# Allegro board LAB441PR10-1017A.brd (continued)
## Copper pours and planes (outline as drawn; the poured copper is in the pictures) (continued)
LG_5V on BOTTOM (solid shape): 61.56,53.99 61.82,53.99 61.94,53.86 61.94,52.97 61.82,52.85 61.43,52.85 60.35,53.93 60.35,54.12 60.42,54.18 61.37,54.18
LG_5V on IN3 (solid shape): 62.83,53.29 62.83,52.47 62.7,52.34 62.01,52.34 61.43,52.91 61.43,53.93 61.56,54.05 62.07,54.05
LG_5V on IN3 (solid shape): 68.8,49.73 68.8,48.46 68.67,48.34 68.42,48.34 67.15,49.61 67.15,50.12 67.53,50.5 68.04,50.5
LX_1.05V on TOP (solid shape): 204.31,59.64 204.31,57.48 204.18,57.35 203.29,57.35 203.17,57.48 203.17,59.64 203.29,59.77 204.18,59.77
LX_1.05V on BOTTOM (solid shape): 201.13,61.16 201.77,60.53 204.06,60.53 205.07,59.51 205.07,55.58 204.82,55.32 200.63,55.32 199.99,55.96 199.99,62.43 201.13,62.43
LX_3V on BOTTOM (solid shape): 65.37,56.72 65.37,56.28 64.8,55.7 64.42,55.7 64.29,55.83 64.29,56.78 64.36,56.85 65.24,56.85
LX_3V on BOTTOM (solid shape): 59.15,59.2 59.15,58.18 59.47,57.86 59.47,55.89 59.4,55.83 59.34,55.83 59.28,55.89 59.28,56.91 58.89,57.29 58.89,57.67 58.39,58.18 58.39,59.2 58.45,59.26 59.08,59.26
LX_3V on IN4 (solid shape): 64.86,57.61 64.86,55.83 64.74,55.7 64.36,55.7 64.1,55.96 64.1,56.85 63.72,57.23 63.72,57.48 64.23,57.99 64.48,57.99
LX_3V on IN4 (solid shape): 60.16,58.62 60.16,58.24 59.66,57.74 59.66,57.35 59.4,57.1 59.02,57.1 58.89,57.23 58.89,57.61 58.64,57.86 58.64,58.24 59.4,59.01 59.78,59.01
LX_5V on BOTTOM (solid shape): 70.01,53.35 70.01,52.97 69.82,52.78 68.42,52.78 68.29,52.91 68.29,53.35 68.42,53.48 69.88,53.48
LX_5V on BOTTOM (solid shape): 59.47,53.8 59.47,52.78 59.59,52.66 59.59,51.58 59.72,51.45 59.72,50.88 59.66,50.81 59.15,50.81 59.08,50.88 59.08,52.59 59.28,52.78 59.28,53.8 59.34,53.86 59.4,53.86
LX_5V on IN4 (solid shape): 59.66,52.66 59.66,51.89 60.16,51.39 60.16,50.88 59.78,50.5 59.53,50.5 59.02,51 59.02,52.66 59.15,52.78 59.53,52.78
LX_5V on IN4 (solid shape): 70.01,53.29 70.01,52.15 69.82,51.96 69.05,51.96 68.86,52.15 68.86,53.23 68.99,53.35 69.94,53.35
LX_CORE on TOP (solid shape): 94.26,59.7 94.26,58.24 94.07,58.05 92.68,58.05 92.42,58.31 92.42,59.77 92.49,59.83 94.14,59.83
LX_CORE on BOTTOM (solid shape): 95.72,59.45 95.72,55.89 96.61,55.89 96.61,58.82 96.8,59.01 98.33,59.01 98.96,58.37 98.96,55.07 98.39,54.5 92.49,54.5 91.22,55.77 91.22,56.81 91.03,57 91.03,59.96 95.22,59.96
MIC1_L on TOP (solid shape): 27.13,27.87 27.93,27.87 27.93,27.86 28.3,27.86 28.36,27.79 28.36,27.72 28.29,27.64 25.92,27.64 25.82,27.74 25.82,28.01 25.9,28.09 26.9,28.09
MIC1_L on BOTTOM (solid shape): 14.23,24.46 14.23,23.74 14.08,23.58 11.9,23.58 11.9,23.59 11.34,23.59 11.34,23.58 11.3,23.58 11.18,23.7 11.18,24.44 11.38,24.63 14.06,24.63
MIC1_L on IN2 (solid shape): 15.19,24.58 15.19,23.8 14.98,23.59 13.32,23.59 13.14,23.77 13.14,24.51 13.34,24.7 15.07,24.7
MIC1_L on IN2 (solid shape): 24.99,28.66 25.21,28.5 25.46,28.56 25.5,28.58 25.98,28.1 26.69,28.1 26.84,27.96 26.84,27.78 26.7,27.64 24.82,27.64 24.82,27.64 24.48,27.64 24.36,27.76 24.36,28.52 24.49,28.66
MIC1_L_L on TOP (solid shape): 12.12,23.65 12.12,22.4 11.93,22.21 11.17,22.21 11,22.39 11,23.55 11.31,23.86 11.91,23.86
MIC1_L_L on TOP (solid shape): 16.45,27.78 16.45,26.42 16.24,26.2 15.66,26.2 15.39,26.47 15.39,27.71 15.59,27.91 16.32,27.91
MIC1_L_L on BOTTOM (solid shape): 6.39,24.6 7.92,24.6 9.01,23.5 9.97,23.5 10.05,23.41 11.13,23.41 11.19,23.36 11.98,23.36 12.1,23.24 12.1,22.36 11.97,22.23 11.13,22.23 10.86,22.5 8.45,22.5 7.96,22.98 7.96,22.98 7.45,23.49 5.78,23.49 4.87,24.41 3.78,24.41 3.47,24.71 3.47,25.79 3.57,25.89 5.1,25.89
MIC1_R on TOP (solid shape): 9.52,22.58 9.52,21.24 9.43,21.15 8.39,21.15 8.11,21.43 8.11,23.06 8.17,23.12 8.97,23.12
MIC1_R on TOP (solid shape): 27.4,27.49 27.69,27.49 27.71,27.47 28.31,27.47 28.37,27.41 28.37,27.31 28.3,27.23 26.89,27.23 26.71,27.06 25.9,27.06 25.79,27.16 25.79,27.44 25.87,27.52 27.37,27.52
MIC1_R on BOTTOM (solid shape): 12.45,21.62 14.02,21.62 14.25,21.39 14.25,20.59 14.09,20.42 13.01,20.42 13,20.43 12.36,20.79 11.65,21.03 11.64,21.03 11.52,21.15 8.46,21.15 8.29,21.33 8.29,21.88 8.4,21.99 12.08,21.99
MIC1_R on IN2 (solid shape): 15.21,21.34 15.21,20.85 14.76,20.39 13.21,20.39 13.08,20.51 13.08,21.46 13.19,21.57 14.99,21.57
MIC1_R on IN2 (solid shape): 26.86,27.37 26.86,27.21 26.71,27.06 25.75,27.06 25.2,26.51 24.69,26.51 24.53,26.66 24.53,27.43 24.63,27.52 26.7,27.52
MIC1_R_L on TOP (solid shape): 17.99,25.97 18.07,25.89 18.07,24.48 17.99,24.41 17.04,24.41 16.99,24.45 16.99,24.9 17.29,25.2 17.29,25.9 17.36,25.97 17.6,25.97
MIC1_R_L on TOP (solid shape): 8.41,25.78 8.41,25.22 10.78,22.85 10.78,22.43 11.14,22.07 12.19,22.07 12.33,21.93 12.33,21.13 12.21,21.01 11.71,21.01 11.61,21.04 11.52,21.06 11.41,21.16 9.93,21.16 9.75,21.34 9.75,22.53 8.9,23.37 8.31,23.37 8.24,23.3 6.3,23.3 6.16,23.44 6.16,25.78 6.42,26.03 8.16,26.03
PBATT+_C on TOP (solid shape): 73.13,29.6 73.13,27.3 72.73,26.89 70.48,26.89 70.17,27.2 70.17,29.52 70.72,30.07 72.66,30.07
PBATT+_C on BOTTOM (solid shape): 73.77,31.48 73.77,24.29 73.38,23.9 72.69,23.9 71.22,22.43 69.81,22.43 69.69,22.55 69.69,30.67 69.69,30.67 69.78,30.76 72.23,30.76 72.99,31.52 73.73,31.52
SNUB_1.5V on TOP (solid shape): 197.17,66.44 197.17,64.65 197.06,64.54 196.56,64.54 196.51,64.59 196.51,65.27 196.25,65.54 195.64,65.54 195.53,65.64 195.53,66.46 195.57,66.49 197.12,66.49
SPK_L+_C on TOP (solid shape): 28.25,21.61 28.25,20.63 27.85,20.23 26.09,20.23 26.08,20.23 25.73,20.23 24.54,19.05 22.99,19.05 21.94,18 21.94,16.58 21.65,16.29 20.05,16.29 19.86,16.48 19.86,17.67 20.26,18.08 20.6,18.08 21.27,18.75 21.28,18.76 21.42,18.84 21.51,18.98 21.51,18.99 22.28,19.76 23.4,19.76 23.59,19.71 23.77,19.76 23.97,19.76 25.31,21.1 26.74,21.1 26.98,21.34 26.98,21.5 27.14,21.67 28.19,21.67
SPK_L+_C on BOTTOM (solid shape): 27.08,17.82 27.08,16.72 26.86,16.5 25.63,16.5 25.11,17.02 24.02,17.02 23.35,16.34 23.13,16.34 23.13,16.34 19.98,16.34 19.84,16.48 19.84,17.5 20.05,17.7 20.81,17.7 21.18,17.33 23.35,17.33 23.89,17.88 27.02,17.88
SPK_L-_C on TOP (solid shape): 27.79,19.9 28.1,19.9 28.21,19.78 28.21,18.93 27.38,18.1 23.42,18.1 23.13,17.8 23.13,14.51 22.65,14.03 19.91,14.03 19.79,14.14 19.79,15.4 20.02,15.63 22.03,15.63 22.13,15.73 22.13,17.88 23.13,18.88 24.83,18.88 25.14,19.19 26.65,19.19 27.01,19.55 27.01,19.81 27.1,19.9 27.79,19.9
SPK_L-_C on BOTTOM (solid shape): 25.71,16.2 26.94,16.2 27.05,16.09 27.05,15.6 26.94,15.49 25.55,15.49 25.1,15.95 24.12,15.95 22.25,14.08 19.9,14.08 19.8,14.18 19.8,15.41 20.02,15.63 22.89,15.63 24.15,16.89 25.02,16.89
SPK_OUT_L+ on TOP (solid shape): 30.59,24.83 30.59,23.83 30.51,23.75 30.51,23.19 29.11,21.79 29.11,20.59 28.99,20.46 28.41,20.46 28.35,20.52 28.35,21.86 30,23.51 30,23.65 30.33,23.98 30.33,24.82 30.38,24.88 30.54,24.88
SPK_OUT_L- on TOP (solid shape): 31.01,24.76 31.01,22.42 30,21.41 30,19.64 28.99,18.62 28.44,18.62 28.44,19.84 28.55,19.95 29.05,19.95 29.3,20.21 29.3,21.67 30.64,23 30.64,23.7 30.73,23.79 30.73,24.8 30.77,24.85 30.92,24.85
SPK_OUT_R+ on TOP (solid shape): 31.79,24.8 31.79,24 32.54,23.26 32.54,21.35 32.99,20.91 32.99,20.39 32.9,20.3 31.88,20.3 31.84,20.34 31.84,23.64 31.53,23.95 31.53,24.82 31.56,24.86 31.74,24.86
SPK_OUT_R- on TOP (solid shape): 31.39,24.78 31.39,23.9 31.72,23.57 31.72,21.67 31.34,21.29 31.34,20.44 31.18,20.29 30.29,20.29 30.19,20.39 30.19,21.35 31.14,22.3 31.14,24.78 31.21,24.84 31.33,24.84
SPK_R+_C on TOP (solid shape): 33,19.93 33,19.05 32.92,18.97 32.57,18.97 32.38,18.78 32.38,17.39 31.25,16.26 30.05,16.26 27.36,13.57 23.79,13.57 23.58,13.78 23.58,15.09 23.68,15.19 25.52,15.19 25.71,14.99 27.31,14.99 29.61,17.29 31.01,17.29 31.7,17.99 31.7,19.99 31.79,20.07 32.86,20.07
SPK_R+_C on BOTTOM (solid shape): 25.39,14.14 27,14.14 27.08,14.06 27.08,13.61 26.97,13.5 23.96,13.5 23.76,13.71 23.76,14.21 23.9,14.35 25.18,14.35
SPK_R-_C on TOP (solid shape): 31.34,19.99 31.34,19.57 31.34,19.02 31.27,18.95 30.86,18.95 30.64,18.73 30.64,18.18 29.94,17.48 28.73,17.48 27.65,16.39 26,16.39 24.96,15.35 24.75,15.35 24.73,15.35 24.22,15.35 24.2,15.35 23.73,15.35 23.51,15.56 23.51,17.07 23.7,17.26 27.11,17.26 28.29,18.43 29.05,18.43 30.2,19.58 30.2,19.96 30.33,20.1 31.22,20.1
SPK_R-_C on BOTTOM (solid shape): 25.72,15.15 26.89,15.15 27.09,14.95 27.09,14.59 26.94,14.45 25.43,14.45 25.32,14.56 24.24,14.56 24.07,14.73 24.07,15.73 24.17,15.84 25.04,15.84
SW_1.5V on TOP (solid shape): 197.44,74.16 197.44,71.02 196.93,70.99 197.05,70.5 197.05,67.34 196.95,67.23 195.04,67.23 194.96,67.32 194.96,69.31 194.38,69.89 194.38,71.12 194.48,71.22 195.46,71.22 195.93,71.68 195.93,74.2 196.04,74.32 197.29,74.32
SW_1.8V on TOP (solid shape): 39.42,61.94 39.42,60.93 39.25,60.77 39.11,60.77 38.85,60.51 38.85,59.57 38.64,59.37 37.28,59.37 36.73,58.82 35.46,58.82 35.34,58.94 35.34,60.22 35.46,60.35 36.71,60.35 36.91,60.56 36.92,60.56 37.7,61.33 37.7,61.56 38.15,62 39.35,62
SW_1.35V on TOP (solid shape): 83.66,51.07 83.66,49.48 83.6,49.42 82.58,49.42 82.2,49.04 82.2,47.13 82.01,46.94 77.82,46.94 76.99,47.77 76.99,49.61 77.31,49.93 78.01,49.93 78.2,50.12 78.2,50.88 78.33,51 82.14,51 82.33,51.2 83.53,51.2
SW_1.35V on BOTTOM (solid shape): 76.61,52.4 76.61,50.31 76.86,50.05 76.86,49.8 76.74,49.67 75.79,49.67 75.59,49.48 74.53,49.48 74.48,49.53 74.48,49.65 74.57,49.73 75.34,49.73 75.79,50.18 75.79,52.4 75.85,52.47 76.55,52.47
SW_1.35V on BOTTOM (solid shape): 83.6,51.64 83.6,49.42 83.41,49.23 82.58,49.23 82.26,48.91 82.26,47.19 82.07,47 78.58,47 78.13,47.45 78.13,50.88 78.26,51 79.6,51 79.79,51.2 79.79,51.7 79.91,51.83 83.41,51.83
SW_1.35V on IN2 (solid shape): 79.4,50.18 79.4,49.86 79.21,49.67 75.85,49.67 75.72,49.8 75.72,50.18 75.91,50.37 79.21,50.37
UG_3V on BOTTOM (solid shape): 66.04,56.72 66.04,55.04 65.94,54.94 65.63,54.94 65.5,55.07 65.5,56.15 65.56,56.21 65.56,56.72 65.69,56.85 65.92,56.85
UG_3V on BOTTOM (solid shape): 60.67,57.93 60.67,57.67 60.8,57.55 60.8,56.91 60.67,56.78 60.67,56.28 60.23,55.83 60.1,55.83 60.04,55.89 60.04,56.85 60.16,56.97 60.16,57.86 60.29,57.99 60.61,57.99
UG_3V on IN4 (solid shape): 60.8,57.74 60.8,56.72 61.05,56.47 61.05,56.08 60.8,55.83 60.16,55.83 60.04,55.96 60.04,57.74 60.29,57.99 60.55,57.99
UG_3V on IN4 (solid shape): 66.02,55.94 66.02,54.96 65.37,54.31 64.74,54.31 64.48,54.56 64.48,55.07 64.61,55.07 64.86,55.32 65.12,55.32 65.5,55.7 65.5,55.96 65.63,56.08 65.88,56.08
UG_5V on BOTTOM (solid shape): 60.99,53.1 60.99,52.15 60.86,52.02 60.48,52.02 60.35,52.15 60.35,52.59 60.04,52.91 60.04,53.8 60.1,53.86 60.23,53.86
UG_5V on BOTTOM (solid shape): 68.74,53.99 68.74,53.74 68.61,53.61 68.29,53.61 68.1,53.42 68.1,52.91 67.97,52.78 67.72,52.78 67.59,52.91 67.59,53.99 67.72,54.12 68.61,54.12
UG_5V on IN4 (solid shape): 61.56,52.53 61.94,52.53 62.07,52.4 62.07,51.77 61.82,51.51 60.93,51.51 60.29,52.15 60.29,53.04 60.42,53.16 60.93,53.16
UG_5V on IN4 (solid shape): 68.8,54.05 68.8,53.67 68.67,53.54 68.17,53.54 67.8,53.18 66.76,53.18 66.64,53.29 66.64,53.98 66.84,54.18 68.67,54.18
N18244124 on TOP (solid shape): 59.4,29.22 59.4,27.64 59.34,27.57 58.32,27.57 58.26,27.64 58.26,28.4 58.07,28.59 56.99,28.59 56.93,28.65 56.93,29.22 56.99,29.29 59.34,29.29
N48038074 on TOP (solid shape): 35.58,66.31 35.58,65.55 35.84,65.29 39.14,65.29 39.39,65.04 39.39,64.02 39.39,64.02 39.39,63.95 39.37,63.93 38.03,63.93 37.68,64.28 36.47,64.28 36.22,64.02 35.58,64.02 35.37,63.82 35.37,63.34 35.23,63.2 33.79,63.2 33.73,63.26 33.73,64.04 33.92,64.23 34.61,64.23 34.67,64.29 34.67,65.32 34.31,65.67 34.31,66.44 34.44,66.56 35.33,66.56
N48058050 on TOP (solid shape): 92.55,57.16 94.14,57.16 94.2,57.1 94.2,56.08 94.14,56.02 92.01,56.02 91.08,56.96 91.08,57.62 91.13,57.67 92.04,57.67
N48095930 on BOTTOM (solid shape): 68.17,65.27 68.17,59.32 67.97,59.13 65.69,59.13 65.56,59.26 65.56,60.15 65.24,60.47 63.02,60.47 62.45,59.89 62.45,59.26 62.39,59.2 61.05,59.2 60.93,59.32 60.93,60.4 63.4,62.88 63.4,64.97 64.16,65.74 67.7,65.74
N48096170 on BOTTOM (solid shape): 65.69,50.5 67.97,50.5 68.1,50.37 68.1,44.46 67.47,43.83 64.42,43.83 64.04,44.21 64.04,47.93 62.86,49.11 62.86,50.34 63.02,50.5 65.69,50.5
N48096331 on BOTTOM (solid shape): 60.35,60.15 60.35,59.58 60.29,59.51 58.45,59.51 58.39,59.58 58.39,60.15 58.45,60.21 60.29,60.21
N48096357 on BOTTOM (solid shape): 64.1,59.58 64.1,59.01 64.04,58.94 63.53,58.94 62.45,57.86 62.45,57.55 62.32,57.42 61.05,57.42 60.99,57.48 60.99,58.31 61.05,58.37 61.88,58.37 63.15,59.64 64.04,59.64
N48096365 on BOTTOM (solid shape): 64.27,52.07 64.27,50.99 63.91,50.63 62.95,50.63 62.73,50.42 62.73,49.65 62.63,49.55 61.3,49.55 61.18,49.67 61.18,50.43 61.24,50.5 62.04,50.5 62.07,50.53 62.26,50.63 62.36,50.82 62.51,50.97 62.51,51.79 62.88,52.17 64.17,52.17
N48096405 on BOTTOM (solid shape): 63.34,54.88 63.34,54.37 63.15,54.18 62.45,54.18 62.32,54.31 62.32,54.62 62.2,54.75 60.42,54.75 60.35,54.81 60.35,54.94 60.42,55.01 61.69,55.01 61.82,55.13 63.09,55.13
N48096452 on BOTTOM (solid shape): 60.99,50.12 60.99,49.61 60.86,49.48 59.59,49.48 59.08,49.99 59.08,50.5 59.15,50.56 60.55,50.56
N49756069 on BOTTOM (solid shape): 32.41,33.92 32.41,32.78 32.1,32.46 31.27,32.46 30.57,33.16 30.57,33.86 30.7,33.99 32.35,33.99
N50183055 on TOP (solid shape): 45.15,75.75 45.15,75.28 46.47,73.96 46.47,73.35 46.35,73.22 45.52,73.22 45.09,73.66 45.09,74.19 44.65,74.63 43.81,74.63 43.72,74.72 43.72,75.79 43.76,75.83 45.08,75.83
N52142257 on TOP (solid shape): 167.24,62.05 167.24,61.3 167.49,61.05 167.49,59.74 167.42,59.66 166.01,59.66 165.94,59.72 165.94,62.06 166.03,62.15 167.14,62.15
N52893865 on TOP (solid shape): 202.54,22.2 202.54,20.72 202.46,20.63 201.78,20.63 201.38,21.03 200.3,21.03 200.25,21.08 200.25,22.19 200.43,22.36 202.38,22.36
N52893895 on TOP (solid shape): 202.56,19.19 202.56,18.07 202.4,17.92 200.35,17.92 200.26,18 200.26,18.81 200.33,18.88 201.27,18.88 201.69,19.29 202.45,19.29
N52895617 on TOP (solid shape): 50.55,64.05 50.55,62.46 50.47,62.37 49.24,62.37 48.99,62.63 48.54,62.63 48.35,62.82 48.35,63.7 48.77,64.12 50.49,64.12
N52895657 on TOP (solid shape): 50.56,60.96 50.56,60.32 50.55,60.31 50.55,59.92 49.9,59.28 49.48,59.28 49.25,59.51 48.35,59.51 48.16,59.7 48.16,60.59 48.16,60.66 48.23,60.72 49.5,60.72 49.81,61.04 50.48,61.04
N52922903 on TOP (solid shape): 200.46,27.48 201.48,27.48 201.63,27.33 201.63,26.54 201.57,26.48 199.28,26.48 199.23,26.53 199.23,27.88 199.28,27.94 200,27.94
N52922958 on TOP (solid shape): 201.65,25.1 201.65,24.6 201.54,24.48 201.54,22.61 201.47,22.54 200.55,22.54 200.46,22.63 200.46,25.06 200.58,25.17 201.58,25.17
N52925836 on TOP (solid shape): 49.05,57.59 49.05,55.96 48.99,55.89 47.34,55.89 47.15,56.08 46.89,56.08 46.77,56.21 46.77,57.16 46.89,57.29 47.79,57.29 48.21,57.72 48.93,57.72
N52925896 on TOP (solid shape): 49.05,54.43 49.05,53.16 48.42,52.53 46.83,52.53 46.7,52.66 46.7,54.05 46.96,54.31 47.59,54.31 47.85,54.56 48.92,54.56
N52930519 on TOP (solid shape): 38.07,56.15 38.07,54.88 38,54.81 36.9,54.81 36.68,55.03 35.72,55.03 35.58,55.17 35.58,56.61 35.69,56.72 37.49,56.72
N52930575 on TOP (solid shape): 38.07,53.35 38.07,51.63 37.74,51.3 35.73,51.3 35.58,51.45 35.58,52.95 35.7,53.07 36.36,53.07 36.71,53.42 38,53.42
N52934489 on TOP (solid shape): 30.66,38.75 30.66,37.73 30.41,37.48 30.41,36.95 30.25,36.79 29.31,36.79 29.24,36.86 29.24,37.46 29.37,37.59 29.89,37.59 30.03,37.73 30.03,38.76 30.09,38.82 30.59,38.82
N52934545 on TOP (solid shape): 34.04,38.72 34.04,37.93 33.43,37.32 33.43,36.6 33.28,36.45 32.48,36.45 32.31,36.61 32.31,37.47 32.05,37.73 32.05,38.78 32.12,38.86 33.9,38.86
N53579675 on TOP (solid shape): 202.12,33.52 202.12,31.22 202.07,31.17 200.69,31.17 200.65,31.21 200.65,32.07 200.96,32.37 200.96,33.47 201.11,33.62 202.02,33.62
N53579693 on TOP (solid shape): 206.24,33.36 206.24,32.35 206.2,32.32 204.61,32.32 204.18,32.75 203.59,32.75 203.48,32.86 203.48,33.55 203.55,33.62 205.99,33.62
N54037942 on TOP (solid shape): 171.45,71.19 171.45,69.58 170.9,69.03 168.82,69.03 168.67,69.18 168.67,70.06 168.92,70.32 169.81,70.32 169.97,70.47 169.97,71.18 170.02,71.24 171.41,71.24
N54285570 on TOP (solid shape): 164.03,57.73 164.7,57.73 164.74,57.69 164.74,56.7 164.58,56.55 162.92,56.55 162.81,56.66 162.81,57.72 162.9,57.81 163.95,57.81

Small or netless copper shapes (teardrops, artwork), in the pictures only: 32 on TOP, 115 on BOTTOM, 23 on IN1, 112 on IN4

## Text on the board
Ref Des/Silkscreen Bottom: RTC | BATTERY | SPEAKER | H6 | KEYBOARD | BOARD FFC | CAMERA | H11 | H10 | H14 | H15 | TOUCH PAD | H16 | H17 | IOB FPC | DC-IN | SCREEN | TOUCH | FAN | EDP | WIFI+BT | SSD
User.Comments: ZAZ00 | LAB441P | Moopi_Wang | 2014-10-20 | 2015-10-20 | 1.0(A00)
DEVICE_TYPE_TOP: FIGURE | SIZE | 8.0 | 10.0 | 21.0 | 26.0 | 31.0 | 79.0 | 130.0 | 40.0 | 43.0 | 63.0 | 71.0 | 51.0x31.0 | 55.0x24.0 | 55.0x28.0 | 75.0x31.0 | 91.0x28.0 | 126.0x31.0 | 91.0x71.0 | DRILL CHART: TOP to BOTTOM | ALL UNITS ARE IN MILS | TOLERANCE | +3.0/-3.0 | +2.0/-2.0 | PLATED | NON-PLATED | QTY | 3118 | 422 | 20 | 2 | 9 | 8 | 7 | 1
USER_PART_NUM_BOTTOM: FIGURE | SIZE | 4.0 | DRILL CHART: GND3 to BOTTOM | ALL UNITS ARE IN MILS | TOLERANCE | +1.0/-1.0 | PLATED | QTY | 446
DEVICE_TYPE_BOTTOM: FIGURE | SIZE | 8.0 | DRILL CHART: GND1 to GND3 | ALL UNITS ARE IN MILS | TOLERANCE | +3.0/-3.0 | PLATED | QTY | 723
COMPVAL_TYPE_TOP: FIGURE | SIZE | 4.0 | DRILL CHART: TOP to GND1 | ALL UNITS ARE IN MILS | TOLERANCE | +1.0/-1.0 | PLATED | QTY | 417
